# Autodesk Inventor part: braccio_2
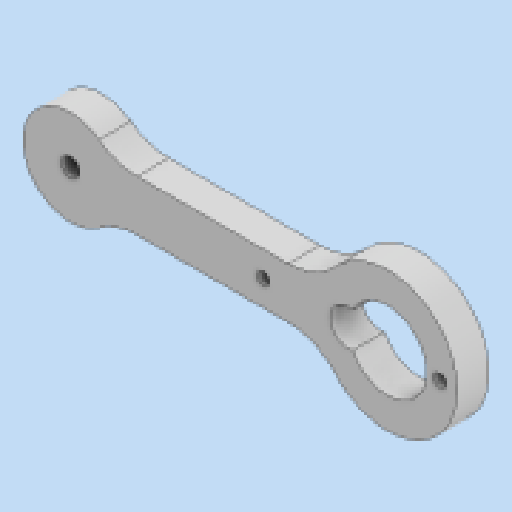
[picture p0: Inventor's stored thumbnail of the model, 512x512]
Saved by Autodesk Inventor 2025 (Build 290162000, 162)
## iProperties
Created: 2026-03
Part Number: braccio_2
Material: Generico
Document SubType Name: Modeling
Designer: Ryzen5700u
Density: 1 g/cm^3
Appearance: Default
Author: Ryzen5700u
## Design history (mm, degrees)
sketch "Schizzo1"
  geometry: L1 (-50, 4)-(0, 4); L2 (0, 4)-(0, -4); L3 (0, -4)-(-50, -4); L4 (-50, -4)-(-50, 4); L5 (0, 0)-(13.023, 0); C1 r 11 at (0, 0); C2 r 7.5 at (-50, 0); 5 further points
  constraints: 10 end point, 2 centre point, 2 horizontal, 2 midpoint, 2 parallel, 1 coincident, 1 perpendicular, 1 other
  dimensions: "d0" = 22 diameter of C1; "d3" = 50 distance of L1.start L1.end; "d4" = 15 diameter of C2; "d16" = 8 distance between parallel lines of L3 L1
extrude "Estrusione1" new body sketch "Schizzo1" distance "d1" = 5; taper "d2" = 0 deg
fillet "Raccordo1" dims "d5" = 10
sketch "Schizzo2"
  geometry: L1 (-0.548, -2.337)-(-0.45, -2.358) reference; L2 (-0.569, -2.434)-(-0.548, -2.337) reference; L3 (-0.694, -2.298)-(-0.725, -2.393) reference; L4 (-0.789, -2.267)-(-0.694, -2.298) reference; L5 (-0.82, -2.362)-(-0.789, -2.267) reference; L6 (-0.93, -2.213)-(-0.971, -2.304) reference; L7 (-1.022, -2.172)-(-0.93, -2.213) reference; L8 (-1.062, -2.263)-(-1.022, -2.172) reference; L9 (-1.157, -2.103)-(-1.206, -2.19) reference; L10 (-1.243, -2.053)-(-1.157, -2.103) reference; L11 (-1.293, -2.14)-(-1.243, -2.053) reference; L12 (-1.37, -1.971)-(-1.429, -2.052) reference; L13 (-1.451, -1.912)-(-1.37, -1.971) reference; L14 (-1.51, -1.993)-(-1.451, -1.912) reference; L15 (-1.569, -1.817)-(-1.635, -1.891) reference; L16 (-1.643, -1.75)-(-1.569, -1.817) reference; L17 (-1.71, -1.824)-(-1.643, -1.75) reference; L18 (-1.75, -1.643)-(-1.824, -1.71) reference; L19 (-1.817, -1.569)-(-1.75, -1.643) reference; L20 (-1.891, -1.635)-(-1.817, -1.569) reference; L21 (-1.912, -1.451)-(-1.993, -1.51) reference; L22 (-1.971, -1.37)-(-1.912, -1.451) reference; L23 (-2.052, -1.429)-(-1.971, -1.37) reference; L24 (-2.053, -1.243)-(-2.14, -1.293) reference; L25 (-2.103, -1.157)-(-2.053, -1.243) reference; L26 (-2.19, -1.206)-(-2.103, -1.157) reference; L27 (-2.172, -1.022)-(-2.263, -1.062) reference; L28 (-2.213, -0.93)-(-2.172, -1.022) reference; L29 (-2.304, -0.971)-(-2.213, -0.93) reference; L30 (-2.267, -0.789)-(-2.362, -0.82) reference; L31 (-2.298, -0.694)-(-2.267, -0.789) reference; L32 (-2.393, -0.725)-(-2.298, -0.694) reference; L33 (-2.337, -0.548)-(-2.434, -0.569) reference; L34 (-2.358, -0.45)-(-2.337, -0.548) reference; L35 (-2.455, -0.471)-(-2.358, -0.45) reference; L36 (-2.382, -0.301)-(-2.481, -0.311) reference; L37 (-2.392, -0.201)-(-2.382, -0.301) reference; L38 (-2.491, -0.212)-(-2.392, -0.201) reference; L39 (-2.4, -0.05)-(-2.499, -0.05) reference; L40 (-2.4, 0.05)-(-2.4, -0.05) reference; L41 (-2.499, 0.05)-(-2.4, 0.05) reference; L42 (-2.392, 0.201)-(-2.491, 0.212) reference; L43 (-2.382, 0.301)-(-2.392, 0.201) reference; L44 (-2.481, 0.311)-(-2.382, 0.301) reference; L45 (-2.358, 0.45)-(-2.455, 0.471) reference; L46 (-2.337, 0.548)-(-2.358, 0.45) reference; L47 (-2.434, 0.569)-(-2.337, 0.548) reference; L48 (-2.298, 0.694)-(-2.393, 0.725) reference; L49 (-2.267, 0.789)-(-2.298, 0.694) reference; L50 (-2.362, 0.82)-(-2.267, 0.789) reference; L51 (-2.213, 0.93)-(-2.304, 0.971) reference; L52 (-2.172, 1.022)-(-2.213, 0.93) reference; L53 (-2.263, 1.062)-(-2.172, 1.022) reference; L54 (-2.103, 1.157)-(-2.19, 1.206) reference; L55 (-2.053, 1.243)-(-2.103, 1.157) reference; L56 (-2.14, 1.293)-(-2.053, 1.243) reference; L57 (-1.971, 1.37)-(-2.052, 1.429) reference; L58 (-1.912, 1.451)-(-1.971, 1.37) reference; L59 (-1.993, 1.51)-(-1.912, 1.451) reference; L60 (-1.817, 1.569)-(-1.891, 1.635) reference; L61 (-1.75, 1.643)-(-1.817, 1.569) reference; L62 (-1.824, 1.71)-(-1.75, 1.643) reference; L63 (-1.643, 1.75)-(-1.71, 1.824) reference; L64 (-1.569, 1.817)-(-1.643, 1.75) reference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; A1 r 6 centre (0, 0) between (-5.416, -2.584) and (-5.416, 2.584) reference; A2 r 2.7 centre (-6.2, 0) between (-5.416, 2.584) and (-5.416, -2.584) reference; A3 r 2.5 centre (0, 0) between (-0.725, -2.393) and (-0.569, -2.434) reference; A4 r 2.5 centre (0, 0) between (-0.971, -2.304) and (-0.82, -2.362) reference; A5 r 2.5 centre (0, 0) between (-1.206, -2.19) and (-1.062, -2.263) reference; A6 r 2.5 centre (0, 0) between (-1.429, -2.052) and (-1.293, -2.14) reference; A7 r 2.5 centre (0, 0) between (-1.635, -1.891) and (-1.51, -1.993) reference; A8 r 2.5 centre (0, 0) between (-1.824, -1.71) and (-1.71, -1.824) reference; A9 r 2.5 centre (0, 0) between (-1.993, -1.51) and (-1.891, -1.635) reference; A10 r 2.5 centre (0, 0) between (-2.14, -1.293) and (-2.052, -1.429) reference; A11 r 2.5 centre (0, 0) between (-2.263, -1.062) and (-2.19, -1.206) reference; A12 r 2.5 centre (0, 0) between (-2.362, -0.82) and (-2.304, -0.971) reference; A13 r 2.5 centre (0, 0) between (-2.434, -0.569) and (-2.393, -0.725) reference; A14 r 2.5 centre (0, 0) between (-2.481, -0.311) and (-2.455, -0.471) reference; A15 r 2.5 centre (0, 0) between (-2.499, -0.05) and (-2.491, -0.212) reference; A16 r 2.5 centre (0, 0) between (-2.491, 0.212) and (-2.499, 0.05) reference; A17 r 2.5 centre (0, 0) between (-2.455, 0.471) and (-2.481, 0.311) reference; A18 r 2.5 centre (0, 0) between (-2.393, 0.725) and (-2.434, 0.569) reference; A19 r 2.5 centre (0, 0) between (-2.304, 0.971) and (-2.362, 0.82) reference; A20 r 2.5 centre (0, 0) between (-2.19, 1.206) and (-2.263, 1.062) reference; A21 r 2.5 centre (0, 0) between (-2.052, 1.429) and (-2.14, 1.293) reference; A22 r 2.5 centre (0, 0) between (-1.891, 1.635) and (-1.993, 1.51) reference; A23 r 2.5 centre (0, 0) between (-1.71, 1.824) and (-1.824, 1.71) reference; A24 r 2.5 centre (0, 0) between (-1.51, 1.993) and (-1.635, 1.891) reference; A25 r 2.5 centre (0, 0) between (-1.293, 2.14) and (-1.429, 2.052) reference; A26 r 2.5 centre (0, 0) between (-1.062, 2.263) and (-1.206, 2.19) reference; A27 r 2.5 centre (0, 0) between (-0.82, 2.362) and (-0.971, 2.304) reference; A28 r 2.5 centre (0, 0) between (-0.569, 2.434) and (-0.725, 2.393) reference; A29 r 2.5 centre (0, 0) between (-0.311, 2.481) and (-0.471, 2.455) reference; A30 r 2.5 centre (0, 0) between (-0.05, 2.499) and (-0.212, 2.491) reference; A31 r 2.5 centre (0, 0) between (0.212, 2.491) and (0.05, 2.499) reference; A32 r 2.5 centre (0, 0) between (0.471, 2.455) and (0.311, 2.481) reference; A33 r 2.5 centre (0, 0) between (0.725, 2.393) and (0.569, 2.434) reference; A34 r 2.5 centre (0, 0) between (0.971, 2.304) and (0.82, 2.362) reference; A35 r 2.5 centre (0, 0) between (1.206, 2.19) and (1.062, 2.263) reference; A36 r 2.5 centre (0, 0) between (1.429, 2.052) and (1.293, 2.14) reference; A37 r 2.5 centre (0, 0) between (1.635, 1.891) and (1.51, 1.993) reference; A38 r 2.5 centre (0, 0) between (1.824, 1.71) and (1.71, 1.824) reference; A39 r 2.5 centre (0, 0) between (1.993, 1.51) and (1.891, 1.635) reference; A40 r 2.5 centre (0, 0) between (2.14, 1.293) and (2.052, 1.429) reference; A41 r 2.5 centre (0, 0) between (2.263, 1.062) and (2.19, 1.206) reference; A42 r 2.5 centre (0, 0) between (2.362, 0.82) and (2.304, 0.971) reference; A43 r 2.5 centre (0, 0) between (2.434, 0.569) and (2.393, 0.725) reference; A44 r 2.5 centre (0, 0) between (2.481, 0.311) and (2.455, 0.471) reference; A45 r 2.5 centre (0, 0) between (2.499, 0.05) and (2.491, 0.212) reference; A46 r 2.5 centre (0, 0) between (2.491, -0.212) and (2.499, -0.05) reference; A47 r 2.5 centre (0, 0) between (2.455, -0.471) and (2.481, -0.311) reference; A48 r 2.5 centre (0, 0) between (2.393, -0.725) and (2.434, -0.569) reference; A49 r 2.5 centre (0, 0) between (2.304, -0.971) and (2.362, -0.82) reference; A50 r 2.5 centre (0, 0) between (2.19, -1.206) and (2.263, -1.062) reference; A51 r 2.5 centre (0, 0) between (2.052, -1.429) and (2.14, -1.293) reference; A52 r 2.5 centre (0, 0) between (1.891, -1.635) and (1.993, -1.51) reference; A53 r 2.5 centre (0, 0) between (1.71, -1.824) and (1.824, -1.71) reference; A54 r 2.5 centre (0, 0) between (1.51, -1.993) and (1.635, -1.891) reference; A55 r 2.5 centre (0, 0) between (1.293, -2.14) and (1.429, -2.052) reference; A56 r 2.5 centre (0, 0) between (1.062, -2.263) and (1.206, -2.19) reference; A57 r 2.5 centre (0, 0) between (0.82, -2.362) and (0.971, -2.304) reference; A58 r 2.5 centre (0, 0) between (0.569, -2.434) and (0.725, -2.393) reference; A59 r 2.5 centre (0, 0) between (0.311, -2.481) and (0.471, -2.455) reference; A60 r 2.5 centre (0, 0) between (0.05, -2.499) and (0.212, -2.491) reference; A61 r 2.5 centre (0, 0) between (-0.212, -2.491) and (-0.05, -2.499) reference; A62 r 2.5 centre (0, 0) between (-0.471, -2.455) and (-0.311, -2.481) reference; A63 r 6.15 centre (0, 0) between (-5.495, -2.762) and (-5.495, 2.762); A64 r 2.85 centre (-6.2, 0) between (-5.495, 2.762) and (-5.495, -2.762); 1 further point
  constraints: 4 point on circle, 2 centre point, 1 other
  dimensions: "d6" = 0.15 radial gap between concentric circles of A1 A63
extrude "Estrusione2" cut sketch "Schizzo2" extent not by distance; stored distance "d7" = 0; taper "d8" = 0 deg
sketch "Schizzo3"
  geometry: A1 r 7.5 centre (50, 0) between (45.5, -6) and (45.5, 6) reference; 2 further points
  constraints: 1 coincident
hole "Foro1" sketch "Schizzo3" at (50, 0) diameter "d9" = 2.9; stored, may be unused: countersink angle "d13" = 82 deg, drill point angle "d15" = 118 deg; dims "d10" = 6, "d11" = 4.5, "d12" = 2, "d14" = 8
sketch "Schizzo4"
  geometry: A1 r 1 centre (19.55, 0) between (20.35, 0.6) and (20.35, -0.6) reference; A2 r 1 centre (-8.25, 0) between (-9.05, -0.6) and (-9.05, 0.6) reference; 1 further point
hole "Foro2" sketch "Schizzo4" at (19.55, 0), (-8.25, 0) diameter "d17" = 2; stored, may be unused: countersink angle "d21" = 90 deg, drill point angle "d23" = 118 deg; dims "d18" = 6, "d19" = 4, "d20" = 2, "d22" = 8
node "Solido1"
node "Riferimento1"
node "Riferimento2"
node "Riferimento3"
